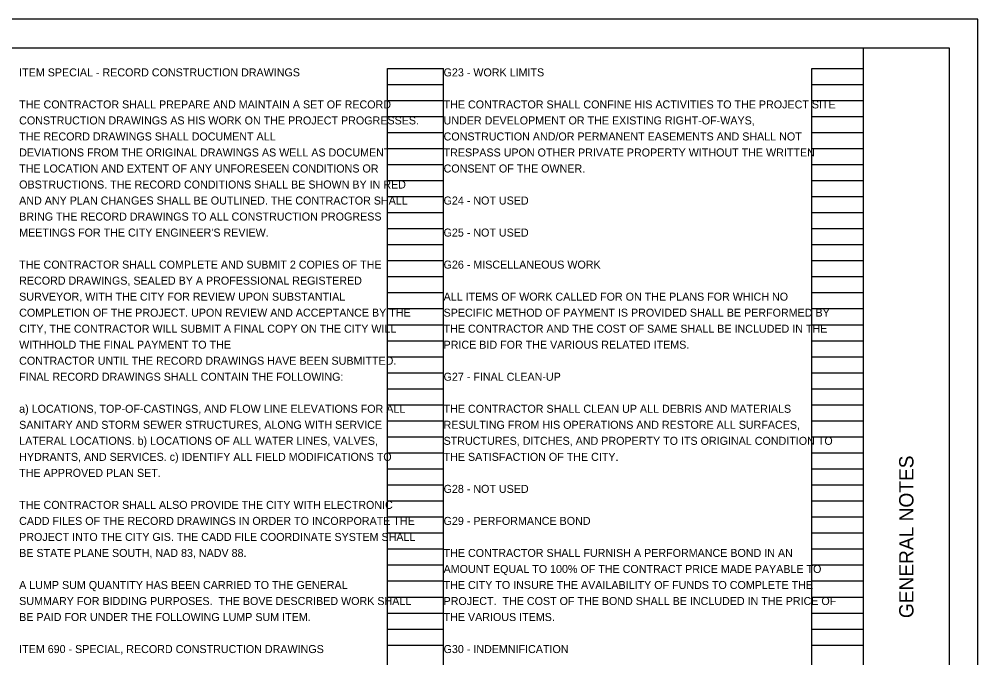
# Model space of a CAD drawing. Extents: x 0 to 37.1, y 0 to 22.
# Drawn here: x 17.24 to 34, y 10.84 to 22 of the extents above; entities that cross this region are included whole.
import ezdxf

# ---------------------------------------------------------------- set-up
doc = ezdxf.new("R2010")
doc.units = 0
for name, color, linetype in [('SH_Border', 7, 'Continuous'), ('SH_Cut_Line', 7, 'Continuous'), ('SH_Data', 7, 'Continuous'), ('SH_Text', 7, 'Continuous')]:
    doc.layers.add(name, color=color, linetype=linetype)

msp = doc.modelspace()

# ---------------------------------------------------------------- linework, layer by layer
at = {"layer": 'SH_Border'}
msp.add_line((32, 0.5), (32, 21.5), dxfattribs=at)
msp.add_lwpolyline([(1.5, 21.5), (33.5, 21.5), (33.5, 0.5), (1.5, 0.5)], close=True, dxfattribs=at)
at = {"layer": 'SH_Cut_Line'}
msp.add_lwpolyline([(0, 0), (34, 0), (34, 22), (0, 22)], close=True, dxfattribs=at)
at = {"layer": 'SH_Data'}
for p, q in [((23.68, 0.98), (23.68, 21.14)), ((23.68, 21.14), (24.66, 21.14)), ((24.66, 0.98), (24.66, 21.14)), ((31.1, 0.98), (31.1, 21.14)), ((31.1, 21.14), (32, 21.14)), ((32, 0.98), (32, 21.14)), ((23.68, 20.86), (24.66, 20.86)), ((31.1, 20.86), (32, 20.86)), ((23.68, 20.58), (24.66, 20.58)), ((31.1, 20.58), (32, 20.58)), ((23.68, 20.3), (24.66, 20.3)), ((31.1, 20.3), (32, 20.3)), ((23.68, 20.02), (24.66, 20.02)), ((31.1, 20.02), (32, 20.02)), ((23.68, 19.74), (24.66, 19.74)), ((31.1, 19.74), (32, 19.74)), ((23.68, 19.46), (24.66, 19.46)), ((31.1, 19.46), (32, 19.46)), ((23.68, 19.18), (24.66, 19.18)), ((31.1, 19.18), (32, 19.18)), ((23.68, 18.9), (24.66, 18.9)), ((31.1, 18.9), (32, 18.9)), ((23.68, 18.62), (24.66, 18.62)), ((31.1, 18.62), (32, 18.62)), ((23.68, 18.34), (24.66, 18.34)), ((31.1, 18.34), (32, 18.34)), ((23.68, 18.06), (24.66, 18.06)), ((31.1, 18.06), (32, 18.06)), ((23.68, 17.78), (24.66, 17.78)), ((31.1, 17.78), (32, 17.78)), ((23.68, 17.5), (24.66, 17.5)), ((31.1, 17.5), (32, 17.5)), ((23.68, 17.22), (24.66, 17.22)), ((31.1, 17.22), (32, 17.22)), ((23.68, 16.94), (24.66, 16.94)), ((31.1, 16.94), (32, 16.94)), ((23.68, 16.66), (24.66, 16.66)), ((31.1, 16.66), (32, 16.66)), ((23.68, 16.38), (24.66, 16.38)), ((31.1, 16.38), (32, 16.38)), ((23.68, 16.1), (24.66, 16.1)), ((31.1, 16.1), (32, 16.1)), ((23.68, 15.82), (24.66, 15.82)), ((31.1, 15.82), (32, 15.82)), ((23.68, 15.54), (24.66, 15.54)), ((31.1, 15.54), (32, 15.54)), ((23.68, 15.26), (24.66, 15.26)), ((31.1, 15.26), (32, 15.26)), ((23.68, 14.98), (24.66, 14.98)), ((31.1, 14.98), (32, 14.98)), ((23.68, 14.7), (24.66, 14.7)), ((31.1, 14.7), (32, 14.7)), ((23.68, 14.42), (24.66, 14.42)), ((31.1, 14.42), (32, 14.42)), ((23.68, 14.14), (24.66, 14.14)), ((31.1, 14.14), (32, 14.14)), ((23.68, 13.86), (24.66, 13.86)), ((31.1, 13.86), (32, 13.86)), ((23.68, 13.58), (24.66, 13.58)), ((31.1, 13.58), (32, 13.58)), ((23.68, 13.3), (24.66, 13.3)), ((31.1, 13.3), (32, 13.3)), ((23.68, 13.02), (24.66, 13.02)), ((31.1, 13.02), (32, 13.02)), ((23.68, 12.74), (24.66, 12.74)), ((31.1, 12.74), (32, 12.74)), ((23.68, 12.46), (24.66, 12.46)), ((31.1, 12.46), (32, 12.46)), ((23.68, 12.18), (24.66, 12.18)), ((31.1, 12.18), (32, 12.18)), ((23.68, 11.9), (24.66, 11.9)), ((31.1, 11.9), (32, 11.9)), ((23.68, 11.62), (24.66, 11.62)), ((31.1, 11.62), (32, 11.62)), ((23.68, 11.34), (24.66, 11.34)), ((31.1, 11.34), (32, 11.34)), ((23.68, 11.06), (24.66, 11.06)), ((31.1, 11.06), (32, 11.06))]:
    msp.add_line(p, q, dxfattribs=at)

# ---------------------------------------------------------------- texts
msp.add_text('GENERAL NOTES', height=0.25, rotation=90, dxfattribs=at).set_placement((32.875, 11.531))
at = {"layer": 'SH_Text'}
for s, p in [('ITEM SPECIAL - RECORD CONSTRUCTION DRAWINGS', (17.24, 21)), ('G23 - WORK LIMITS', (24.66, 21)), ('THE CONTRACTOR SHALL PREPARE AND MAINTAIN A SET OF RECORD ', (17.24, 20.44)), ('THE CONTRACTOR SHALL CONFINE HIS ACTIVITIES TO THE PROJECT SITE ', (24.66, 20.44)), ('CONSTRUCTION DRAWINGS AS HIS WORK ON THE PROJECT PROGRESSES. ', (17.24, 20.16)), ('UNDER DEVELOPMENT OR THE EXISTING RIGHT-OF-WAYS, ', (24.66, 20.16)), ('THE RECORD DRAWINGS SHALL DOCUMENT ALL ', (17.24, 19.88)), ('CONSTRUCTION AND/OR PERMANENT EASEMENTS AND SHALL NOT ', (24.66, 19.88)), ('DEVIATIONS FROM THE ORIGINAL DRAWINGS AS WELL AS DOCUMENT ', (17.24, 19.6)), ('TRESPASS UPON OTHER PRIVATE PROPERTY WITHOUT THE WRITTEN ', (24.66, 19.6)), ('THE LOCATION AND EXTENT OF ANY UNFORESEEN CONDITIONS OR ', (17.24, 19.32)), ('CONSENT OF THE OWNER. ', (24.66, 19.32)), ('OBSTRUCTIONS. THE RECORD CONDITIONS SHALL BE SHOWN BY IN RED ', (17.24, 19.04)), ('AND ANY PLAN CHANGES SHALL BE OUTLINED. THE CONTRACTOR SHALL ', (17.24, 18.76)), ('G24 - NOT USED', (24.66, 18.76)), ('BRING THE RECORD DRAWINGS TO ALL CONSTRUCTION PROGRESS ', (17.24, 18.48)), ("MEETINGS FOR THE CITY ENGINEER'S REVIEW.", (17.24, 18.2)), ('G25 - NOT USED', (24.66, 18.2)), ('THE CONTRACTOR SHALL COMPLETE AND SUBMIT 2 COPIES OF THE ', (17.24, 17.64)), ('G26 - MISCELLANEOUS WORK', (24.66, 17.64)), ('RECORD DRAWINGS, SEALED BY A PROFESSIONAL REGISTERED ', (17.24, 17.36)), ('SURVEYOR, WITH THE CITY FOR REVIEW UPON SUBSTANTIAL ', (17.24, 17.08)), ('ALL ITEMS OF WORK CALLED FOR ON THE PLANS FOR WHICH NO ', (24.66, 17.08)), ('COMPLETION OF THE PROJECT. UPON REVIEW AND ACCEPTANCE BY THE ', (17.24, 16.8)), ('SPECIFIC METHOD OF PAYMENT IS PROVIDED SHALL BE PERFORMED BY ', (24.66, 16.8)), ('CITY, THE CONTRACTOR WILL SUBMIT A FINAL COPY ON THE CITY WILL ', (17.24, 16.52)), ('THE CONTRACTOR AND THE COST OF SAME SHALL BE INCLUDED IN THE ', (24.66, 16.52)), ('WITHHOLD THE FINAL PAYMENT TO THE ', (17.24, 16.24)), ('PRICE BID FOR THE VARIOUS RELATED ITEMS. ', (24.66, 16.24)), ('CONTRACTOR UNTIL THE RECORD DRAWINGS HAVE BEEN SUBMITTED.  ', (17.24, 15.96)), ('FINAL RECORD DRAWINGS SHALL CONTAIN THE FOLLOWING:', (17.24, 15.68)), ('G27 - FINAL CLEAN-UP', (24.66, 15.68)), ('a) LOCATIONS, TOP-OF-CASTINGS, AND FLOW LINE ELEVATIONS FOR ALL ', (17.24, 15.12)), ('THE CONTRACTOR SHALL CLEAN UP ALL DEBRIS AND MATERIALS ', (24.66, 15.12)), ('SANITARY AND STORM SEWER STRUCTURES, ALONG WITH SERVICE ', (17.24, 14.84)), ('RESULTING FROM HIS OPERATIONS AND RESTORE ALL SURFACES, ', (24.66, 14.84)), ('LATERAL LOCATIONS. b) LOCATIONS OF ALL WATER LINES, VALVES, ', (17.24, 14.56)), ('STRUCTURES, DITCHES, AND PROPERTY TO ITS ORIGINAL CONDITION TO ', (24.66, 14.56)), ('HYDRANTS, AND SERVICES. c) IDENTIFY ALL FIELD MODIFICATIONS TO ', (17.24, 14.28)), ('THE SATISFACTION OF THE CITY.', (24.66, 14.28)), ('THE APPROVED PLAN SET.', (17.24, 14)), ('G28 - NOT USED', (24.66, 13.72)), ('THE CONTRACTOR SHALL ALSO PROVIDE THE CITY WITH ELECTRONIC ', (17.24, 13.44)), ('CADD FILES OF THE RECORD DRAWINGS IN ORDER TO INCORPORATE THE ', (17.24, 13.16)), ('G29 - PERFORMANCE BOND', (24.66, 13.16)), ('PROJECT INTO THE CITY GIS. THE CADD FILE COORDINATE SYSTEM SHALL ', (17.24, 12.88)), ('BE STATE PLANE SOUTH, NAD 83, NADV 88.', (17.24, 12.6)), ('THE CONTRACTOR SHALL FURNISH A PERFORMANCE BOND IN AN ', (24.66, 12.6)), ('AMOUNT EQUAL TO 100% OF THE CONTRACT PRICE MADE PAYABLE TO ', (24.66, 12.32)), ('A LUMP SUM QUANTITY HAS BEEN CARRIED TO THE GENERAL ', (17.24, 12.04)), ('THE CITY TO INSURE THE AVAILABILITY OF FUNDS TO COMPLETE THE ', (24.66, 12.04)), ('SUMMARY FOR BIDDING PURPOSES.  THE BOVE DESCRIBED WORK SHALL ', (17.24, 11.76)), ('PROJECT.  THE COST OF THE BOND SHALL BE INCLUDED IN THE PRICE OF ', (24.66, 11.76)), ('BE PAID FOR UNDER THE FOLLOWING LUMP SUM ITEM.', (17.24, 11.48)), ('THE VARIOUS ITEMS.', (24.66, 11.48)), ('ITEM 690 - SPECIAL, RECORD CONSTRUCTION DRAWINGS', (17.24, 10.92)), ('G30 - INDEMNIFICATION', (24.66, 10.92))]:
    msp.add_text(s, height=0.14, dxfattribs=at).set_placement(p)

doc.saveas('drawing.dxf')
